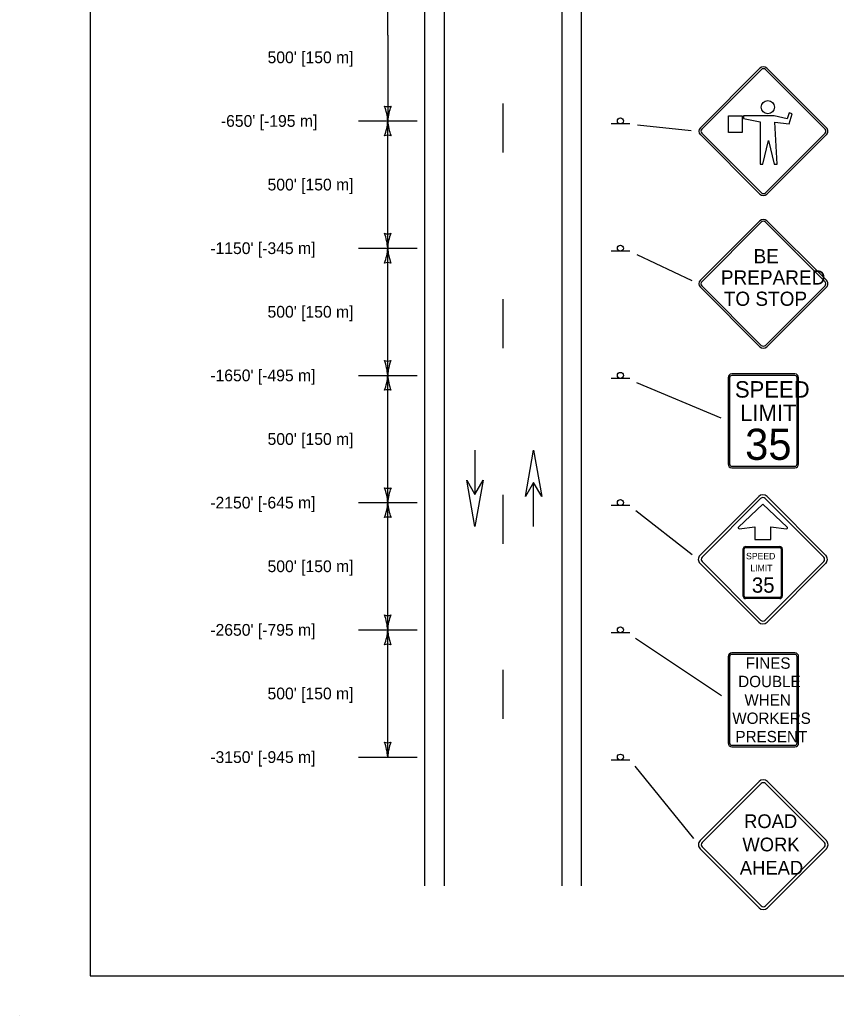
# Model space of a CAD drawing. Extents: x 49991.4 to 50021, y 49987.6 to 50011.4.
# Drawn here: x 49999.98 to 50004.14, y 49999.86 to 50004.95 of the extents above; entities that cross this region are included whole.
import ezdxf

# ---------------------------------------------------------------- set-up
doc = ezdxf.new("R2010")
doc.units = 0
for name, color, linetype in [('Level 1', 7, 'Continuous'), ('Level 2', 7, 'Continuous'), ('Level 3', 7, 'Continuous')]:
    doc.layers.add(name, color=color, linetype=linetype)

msp = doc.modelspace()

# ---------------------------------------------------------------- linework, layer by layer
at = {"layer": 'Level 1'}
for p, q in [((50002.0443, 50000.5232), (50002.0443, 50007.9525)), ((50002.1443, 50001.4605), (50002.1443, 50007.9525)), ((50002.7443, 50001.4605), (50002.7443, 50007.9525)), ((50002.8443, 50000.5232), (50002.8443, 50007.9525)), ((50003.7546, 50004.6997), (50003.4505, 50004.3957)), ((50003.7616, 50004.6928), (50003.4576, 50004.3886)), ((50004.0867, 50004.3886), (50003.7829, 50004.6928)), ((50004.0939, 50004.3957), (50003.7899, 50004.6997)), ((50002.4443, 50004.27), (50002.4443, 50004.52)), ((50003.9029, 50004.4715), (50003.8932, 50004.4414)), ((50003.9194, 50004.4672), (50003.9029, 50004.4715)), ((50003.5939, 50004.3721), (50003.5939, 50004.457)), ((50003.5939, 50004.457), (50003.6633, 50004.457)), ((50003.6633, 50004.457), (50003.6633, 50004.3721)), ((50003.8277, 50004.4566), (50003.6712, 50004.4566)), ((50003.6712, 50004.4566), (50003.6712, 50004.4426)), ((50003.6712, 50004.4426), (50003.7561, 50004.4258)), ((50003.7561, 50004.4258), (50003.7561, 50004.2092)), ((50003.8932, 50004.4414), (50003.8277, 50004.4566)), ((50003.8417, 50004.2092), (50003.8304, 50004.4237)), ((50003.8304, 50004.4237), (50003.9043, 50004.4153)), ((50003.9043, 50004.4153), (50003.9194, 50004.4672)), ((50003.0901, 50004.4153), (50002.9942, 50004.4153)), ((50003.6633, 50004.3721), (50003.5939, 50004.3721)), ((50003.4505, 50004.3605), (50003.7546, 50004.0565)), ((50003.4576, 50004.3675), (50003.7616, 50004.0635)), ((50003.77, 50004.2092), (50003.7989, 50004.3313)), ((50003.7829, 50004.0635), (50004.0867, 50004.3675)), ((50003.7899, 50004.0565), (50004.0939, 50004.3605)), ((50003.7989, 50004.3313), (50003.8279, 50004.2092)), ((50003.7561, 50004.2092), (50003.77, 50004.2092)), ((50003.8279, 50004.2092), (50003.8417, 50004.2092)), ((50003.7545, 50003.9203), (50003.4504, 50003.6163)), ((50003.7615, 50003.9133), (50003.4575, 50003.6092)), ((50004.0866, 50003.6092), (50003.7828, 50003.9133)), ((50004.0938, 50003.6163), (50003.7898, 50003.9203)), ((50003.0901, 50003.7653), (50002.9942, 50003.7653)), ((50003.4504, 50003.581), (50003.7545, 50003.277)), ((50003.4575, 50003.588), (50003.7615, 50003.284)), ((50003.7828, 50003.284), (50004.0866, 50003.588)), ((50003.7898, 50003.277), (50004.0938, 50003.581)), ((50002.4443, 50003.27), (50002.4443, 50003.52)), ((50003.0901, 50003.1153), (50002.9942, 50003.1153)), ((50003.5916, 50003.118), (50003.5916, 50002.678)), ((50003.5992, 50003.118), (50003.5992, 50002.678)), ((50003.9328, 50003.138), (50003.6103, 50003.138)), ((50003.9328, 50003.13), (50003.6103, 50003.13)), ((50003.9441, 50002.678), (50003.9441, 50003.118)), ((50003.9516, 50002.678), (50003.9516, 50003.118)), ((50002.2993, 50002.7483), (50002.2993, 50002.5224)), ((50002.2996, 50002.7483), (50002.2996, 50002.5224)), ((50003.6103, 50002.6661), (50003.9328, 50002.6661)), ((50003.6103, 50002.6581), (50003.9328, 50002.6581)), ((50002.599, 50002.3581), (50002.599, 50002.584)), ((50002.5993, 50002.3581), (50002.5993, 50002.584)), ((50002.4443, 50002.27), (50002.4443, 50002.52)), ((50003.748, 50002.5114), (50003.4487, 50002.2121)), ((50003.7581, 50002.5013), (50003.4588, 50002.202)), ((50003.748, 50002.5114), (50003.748, 50002.5114)), ((50003.7581, 50002.5013), (50003.7581, 50002.5013)), ((50004.0799, 50002.202), (50003.7806, 50002.5013)), ((50004.09, 50002.2121), (50003.7907, 50002.5114)), ((50003.0901, 50002.4654), (50002.9942, 50002.4654)), ((50003.7694, 50002.473), (50003.6449, 50002.3557)), ((50003.8938, 50002.3557), (50003.7694, 50002.473)), ((50003.649, 50002.347), (50003.729, 50002.3571)), ((50003.729, 50002.3571), (50003.729, 50002.2916)), ((50003.8097, 50002.2916), (50003.8097, 50002.3571)), ((50003.8097, 50002.3571), (50003.8897, 50002.347)), ((50003.729, 50002.2916), (50003.8097, 50002.2916)), ((50003.669, 50002.0027), (50003.669, 50002.244)), ((50003.6742, 50002.0027), (50003.6742, 50002.244)), ((50003.6815, 50002.2565), (50003.8562, 50002.2565)), ((50003.6815, 50002.2513), (50003.8562, 50002.2513)), ((50003.7689, 50002.2565), (50003.7689, 50002.2565)), ((50003.8635, 50002.244), (50003.8635, 50002.0027)), ((50003.8687, 50002.244), (50003.8687, 50002.0027)), ((50003.4487, 50002.1694), (50003.748, 50001.8701)), ((50003.4588, 50002.1795), (50003.7581, 50001.8802)), ((50003.7806, 50001.8802), (50004.0799, 50002.1795)), ((50003.7907, 50001.8701), (50004.09, 50002.1694)), ((50003.8562, 50001.9954), (50003.6815, 50001.9954)), ((50003.8562, 50001.9902), (50003.6815, 50001.9902)), ((50003.0901, 50001.8153), (50002.9942, 50001.8153)), ((50003.592, 50001.6926), (50003.592, 50001.2526)), ((50003.5996, 50001.6926), (50003.5996, 50001.2526)), ((50003.9332, 50001.7127), (50003.6108, 50001.7127)), ((50003.9332, 50001.7047), (50003.6108, 50001.7047)), ((50003.9445, 50001.2526), (50003.9445, 50001.6926)), ((50003.952, 50001.2526), (50003.952, 50001.6926)), ((50002.4443, 50001.3757), (50002.4443, 50001.6257)), ((50002.1443, 50000.5232), (50002.1443, 50001.4605)), ((50002.7443, 50000.5232), (50002.7443, 50001.4605)), ((50003.6108, 50001.2408), (50003.9332, 50001.2408)), ((50003.6108, 50001.2327), (50003.9332, 50001.2327)), ((50003.0901, 50001.1653), (50002.9942, 50001.1653)), ((50003.7499, 50001.0555), (50003.449, 50000.7547)), ((50003.7599, 50001.0453), (50003.4592, 50000.7446)), ((50003.7499, 50001.0555), (50003.7499, 50001.0555)), ((50003.7599, 50001.0453), (50003.7599, 50001.0453)), ((50004.0833, 50000.7446), (50003.7826, 50001.0453)), ((50004.0935, 50000.7547), (50003.7928, 50001.0555)), ((50003.449, 50000.7117), (50003.7499, 50000.411)), ((50003.4592, 50000.7219), (50003.7599, 50000.4211)), ((50003.7713, 50000.7332), (50003.7713, 50000.7332)), ((50003.7713, 50000.7332), (50003.7713, 50000.7332)), ((50003.7713, 50000.7332), (50003.7713, 50000.7332)), ((50003.7826, 50000.4211), (50004.0833, 50000.7219)), ((50003.7928, 50000.411), (50004.0935, 50000.7117)), ((49999.9766, 49999.8624), (49999.9766, 49999.8624))]:
    msp.add_line(p, q, dxfattribs=at)
for points in [[(50008.6146, 50011.2628), (50000.3356, 50011.2628), (50000.3356, 50000.0624), (50008.6146, 50000.0624)], [(50002.5573, 50002.5117), (50002.599, 50002.7482), (50002.6409, 50002.5117), (50002.599, 50002.5839)], [(50002.3413, 50002.5947), (50002.2996, 50002.3582), (50002.2577, 50002.5947), (50002.2996, 50002.5225)]]:
    msp.add_lwpolyline(points, close=True, dxfattribs=at)
for points in [[(50003.9027, 50004.4713), (50003.9029, 50004.4715)], [(50003.663, 50004.3721), (50003.6633, 50004.3725)], [(50003.9038, 50004.4154), (50003.9045, 50004.4162)]]:
    msp.add_lwpolyline(points, dxfattribs=at)
for centre, radius in [((50003.7946, 50004.5011), 0.0334), ((50003.0421, 50004.4307), 0.0152), ((50003.0421, 50003.7805), 0.0152), ((50003.0421, 50003.1306), 0.0152), ((50003.0421, 50002.4806), 0.0152), ((50003.0421, 50001.8305), 0.0152), ((50003.0421, 50001.1806), 0.0152)]:
    msp.add_circle(centre, radius, dxfattribs=at)
for centre, radius, start, end in [((50003.7722, 50004.6822), 0.025, 45, 135), ((50003.7722, 50004.6822), 0.015, 45, 135), ((50003.4682, 50004.3781), 0.025, 135, 225), ((50003.4682, 50004.3781), 0.015, 135, 225), ((50004.0762, 50004.3781), 0.015, 315, 45.0002), ((50004.0762, 50004.3781), 0.025, 315, 45.0002), ((50003.7722, 50004.0741), 0.015, 225, 314.9996), ((50003.7722, 50004.0741), 0.025, 225, 314.9996), ((50003.772, 50003.9027), 0.025, 45, 135), ((50003.772, 50003.9027), 0.015, 45, 135), ((50003.468, 50003.5987), 0.025, 135, 225), ((50003.468, 50003.5987), 0.015, 135, 225), ((50004.0761, 50003.5987), 0.015, 315, 45.0002), ((50004.0761, 50003.5987), 0.025, 315, 45.0002), ((50003.772, 50003.2947), 0.025, 225, 314.9996), ((50003.772, 50003.2947), 0.015, 225, 314.9996), ((50003.7694, 50002.4901), 0.0302, 45.0001, 134.9999), ((50003.7694, 50002.4901), 0.016, 45.0001, 134.9999), ((50003.6485, 50002.3521), 0.00508, 134.6287, 275.8295), ((50003.8902, 50002.3521), 0.00509, 264.3826, 45.1649), ((50003.6815, 50002.244), 0.0125, 90, 180), ((50003.6815, 50002.244), 0.00728, 90, 180), ((50003.8562, 50002.244), 0.0125, 360, 90), ((50003.8562, 50002.244), 0.00728, 360, 90), ((50003.4701, 50002.1908), 0.0302, 134.9999, 225.0001), ((50003.4701, 50002.1908), 0.016, 134.9999, 225.0001), ((50004.0687, 50002.1908), 0.016, 314.9999, 45.0001), ((50004.0687, 50002.1908), 0.0302, 314.9999, 45.0001), ((50003.6815, 50002.0027), 0.0125, 180, 270), ((50003.6815, 50002.0027), 0.00728, 180, 270), ((50003.8562, 50002.0027), 0.00728, 270, 360), ((50003.8562, 50002.0027), 0.0125, 270, 360), ((50003.7694, 50001.8915), 0.016, 225.0001, 314.9999), ((50003.7694, 50001.8915), 0.0302, 225.0001, 314.9999), ((50003.7712, 50001.0338), 0.0304, 45.0001, 134.9999), ((50003.7712, 50001.0338), 0.016, 45.0001, 134.9999), ((50003.4705, 50000.7331), 0.0304, 134.9999, 225.0001), ((50003.4705, 50000.7331), 0.016, 134.9999, 225.0001), ((50004.0719, 50000.7331), 0.016, 314.9999, 45.0001), ((50004.0719, 50000.7331), 0.0304, 314.9999, 45.0001), ((50003.7712, 50000.4323), 0.0304, 225.0001, 314.9999), ((50003.7712, 50000.4323), 0.016, 225.0001, 314.9999)]:
    msp.add_arc(centre, radius, start, end, dxfattribs=at)
for centre, major_axis, start_param, end_param in [((50003.6105, 50003.1181), (0, 0.02), 0, 1.570796), ((50003.6105, 50003.1181), (0, 0.012), 0, 1.570796), ((50003.933, 50003.1181), (0, 0.02), 4.712389, 6.283185), ((50003.933, 50003.1181), (0, 0.012), 4.712389, 6.283185), ((50003.6105, 50002.6782), (0, -0.02), 4.712389, 6.283185), ((50003.6105, 50002.6782), (0, -0.012), 4.712389, 6.283185), ((50003.933, 50002.6782), (0, -0.02), 0, 1.570796), ((50003.933, 50002.6782), (0, -0.012), 0, 1.570796), ((50003.6107, 50001.6928), (0, 0.02), 0, 1.570796), ((50003.6107, 50001.6928), (0, 0.012), 0, 1.570796), ((50003.9332, 50001.6928), (0, 0.02), 4.712389, 6.283185), ((50003.9332, 50001.6928), (0, 0.012), 4.712389, 6.283185), ((50003.6107, 50001.2528), (0, -0.02), 4.712389, 6.283185), ((50003.6107, 50001.2528), (0, -0.012), 4.712389, 6.283185), ((50003.9332, 50001.2528), (0, -0.02), 0, 1.570796), ((50003.9332, 50001.2528), (0, -0.012), 0, 1.570796)]:
    msp.add_ellipse(centre, major_axis=major_axis, ratio=0.9375, start_param=start_param, end_param=end_param, dxfattribs=at)
at = {"layer": 'Level 3'}
for p, q in [((50001.8543, 50004.8684), (50001.8542, 50005.0805)), ((50001.8543, 50004.8684), (50001.8543, 50004.4305)), ((50001.7043, 50004.4305), (50002.0043, 50004.4305)), ((50001.854, 50003.7805), (50001.8543, 50004.4305)), ((50003.1299, 50004.4111), (50003.4034, 50004.3823)), ((50001.7043, 50003.7805), (50002.0043, 50003.7805)), ((50001.854, 50003.1305), (50001.854, 50003.7805)), ((50003.1262, 50003.7481), (50003.4068, 50003.6157)), ((50001.7043, 50003.1305), (50002.0043, 50003.1305)), ((50001.8543, 50002.4805), (50001.854, 50003.1305)), ((50003.1241, 50003.0942), (50003.5547, 50002.9135)), ((50001.7043, 50002.4805), (50002.0043, 50002.4805)), ((50001.854, 50001.8305), (50001.8543, 50002.4805)), ((50003.1216, 50002.4407), (50003.4084, 50002.2155)), ((50001.7043, 50001.8305), (50002.0043, 50001.8305)), ((50001.854, 50001.1805), (50001.854, 50001.8305)), ((50003.1187, 50001.7873), (50003.5587, 50001.4947)), ((50001.7043, 50001.1805), (50002.0043, 50001.1805)), ((50003.1153, 50001.1342), (50003.4149, 50000.7642))]:
    msp.add_line(p, q, dxfattribs=at)
for centre, radius, start, end in [((50001.8543, 50004.5587), 0.0548, 252.1388, 287.8612), ((50001.6216, 50004.419), 0.233, 2.8273, 22.0772), ((50002.0764, 50004.4213), 0.2223, 157.456, 177.6395), ((50001.6322, 50004.4396), 0.2223, 337.456, 357.6395), ((50002.087, 50004.442), 0.233, 182.8273, 202.0772), ((50001.8543, 50004.3023), 0.0548, 72.1388, 107.8612), ((50001.854, 50003.9087), 0.0548, 252.1388, 287.8612), ((50001.6213, 50003.769), 0.233, 2.8273, 22.0772), ((50002.0761, 50003.7713), 0.2223, 157.456, 177.6395), ((50001.6319, 50003.7896), 0.2223, 337.456, 357.6395), ((50002.0867, 50003.792), 0.233, 182.8273, 202.0772), ((50001.854, 50003.6523), 0.0548, 72.1388, 107.8612), ((50001.854, 50003.2587), 0.0548, 252.1422, 287.8646), ((50001.6213, 50003.119), 0.233, 2.8307, 22.0805), ((50002.0762, 50003.1213), 0.2223, 157.4594, 177.6429), ((50001.6319, 50003.1396), 0.2223, 337.4785, 357.662), ((50002.0868, 50003.1421), 0.233, 182.8498, 202.0996), ((50001.8541, 50003.0023), 0.0548, 72.1613, 107.8837), ((50001.8542, 50002.6087), 0.0548, 252.1613, 287.8837), ((50001.6216, 50002.4689), 0.233, 2.8498, 22.0996), ((50002.0764, 50002.4714), 0.2223, 157.4785, 177.662), ((50001.6322, 50002.4897), 0.2223, 337.4302, 357.6137), ((50002.087, 50002.4919), 0.233, 182.8015, 202.0513), ((50001.8542, 50002.3523), 0.0548, 72.113, 107.8353), ((50001.8541, 50001.9587), 0.0548, 252.113, 287.8353), ((50001.6213, 50001.8191), 0.233, 2.8015, 22.0513), ((50002.0761, 50001.8212), 0.2223, 157.4302, 177.6137), ((50001.6319, 50001.8396), 0.2223, 337.4594, 357.6429), ((50002.0867, 50001.842), 0.233, 182.8307, 202.0805), ((50001.854, 50001.7023), 0.0548, 72.1422, 107.8646), ((50001.854, 50001.3087), 0.0548, 252.1422, 287.8646), ((50001.6213, 50001.169), 0.233, 2.8307, 22.0805), ((50002.0762, 50001.1713), 0.2223, 157.4594, 177.6429)]:
    msp.add_arc(centre, radius, start, end, dxfattribs=at)

# ---------------------------------------------------------------- texts
at = {"layer": 'Level 1'}
for s, height, p in [('BE', 0.07249, (50003.7219, 50003.7034)), ('PREPARED', 0.07249, (50003.555, 50003.5948)), ('TO STOP', 0.07249, (50003.5697, 50003.4859)), ('SPEED', 0.08409, (50003.6268, 50003.017)), ('LIMIT', 0.08409, (50003.6534, 50002.8969)), ('35', 0.15912, (50003.6789, 50002.6991)), ('FINES', 0.05799, (50003.6823, 50001.6317)), ('DOUBLE', 0.05799, (50003.6436, 50001.5379)), ('WHEN', 0.05799, (50003.6752, 50001.444)), ('WORKERS', 0.05799, (50003.6135, 50001.3501)), ('PRESENT', 0.05799, (50003.6296, 50001.2562)), ('ROAD', 0.07021, (50003.6734, 50000.8178)), ('WORK', 0.07021, (50003.6648, 50000.699)), ('AHEAD', 0.07021, (50003.6517, 50000.5803))]:
    msp.add_text(s, height=height, dxfattribs=at).set_placement(p)
for s, height, p in [('SPEED', 0.03301, (50003.6835, 50002.1908)), ('LIMIT', 0.03301, (50003.7054, 50002.1298)), ('35', 0.07775, (50003.7134, 50002.0204))]:
    msp.add_text(s, height=height, rotation=360, dxfattribs=at).set_placement(p)
at = {"layer": 'Level 2'}
for s, p in [("500' [150 m]", (50001.2408, 50004.7255)), ("-650' [-195 m]", (50001.0024, 50004.4005)), ("500' [150 m]", (50001.2408, 50004.0755)), ("-1150' [-345 m]", (50000.9485, 50003.7505)), ("500' [150 m]", (50001.2406, 50003.4255)), ("-1650' [-495 m]", (50000.9485, 50003.1005)), ("500' [150 m]", (50001.2408, 50002.7755)), ("-2150' [-645 m]", (50000.9485, 50002.4506)), ("500' [150 m]", (50001.2408, 50002.1255)), ("-2650' [-795 m]", (50000.9485, 50001.8005)), ("500' [150 m]", (50001.2406, 50001.4755)), ("-3150' [-945 m]", (50000.9485, 50001.1505))]:
    msp.add_text(s, height=0.06, dxfattribs=at).set_placement(p)

doc.saveas('drawing.dxf')
